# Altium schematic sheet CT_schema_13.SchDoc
size 387 x 385 mm
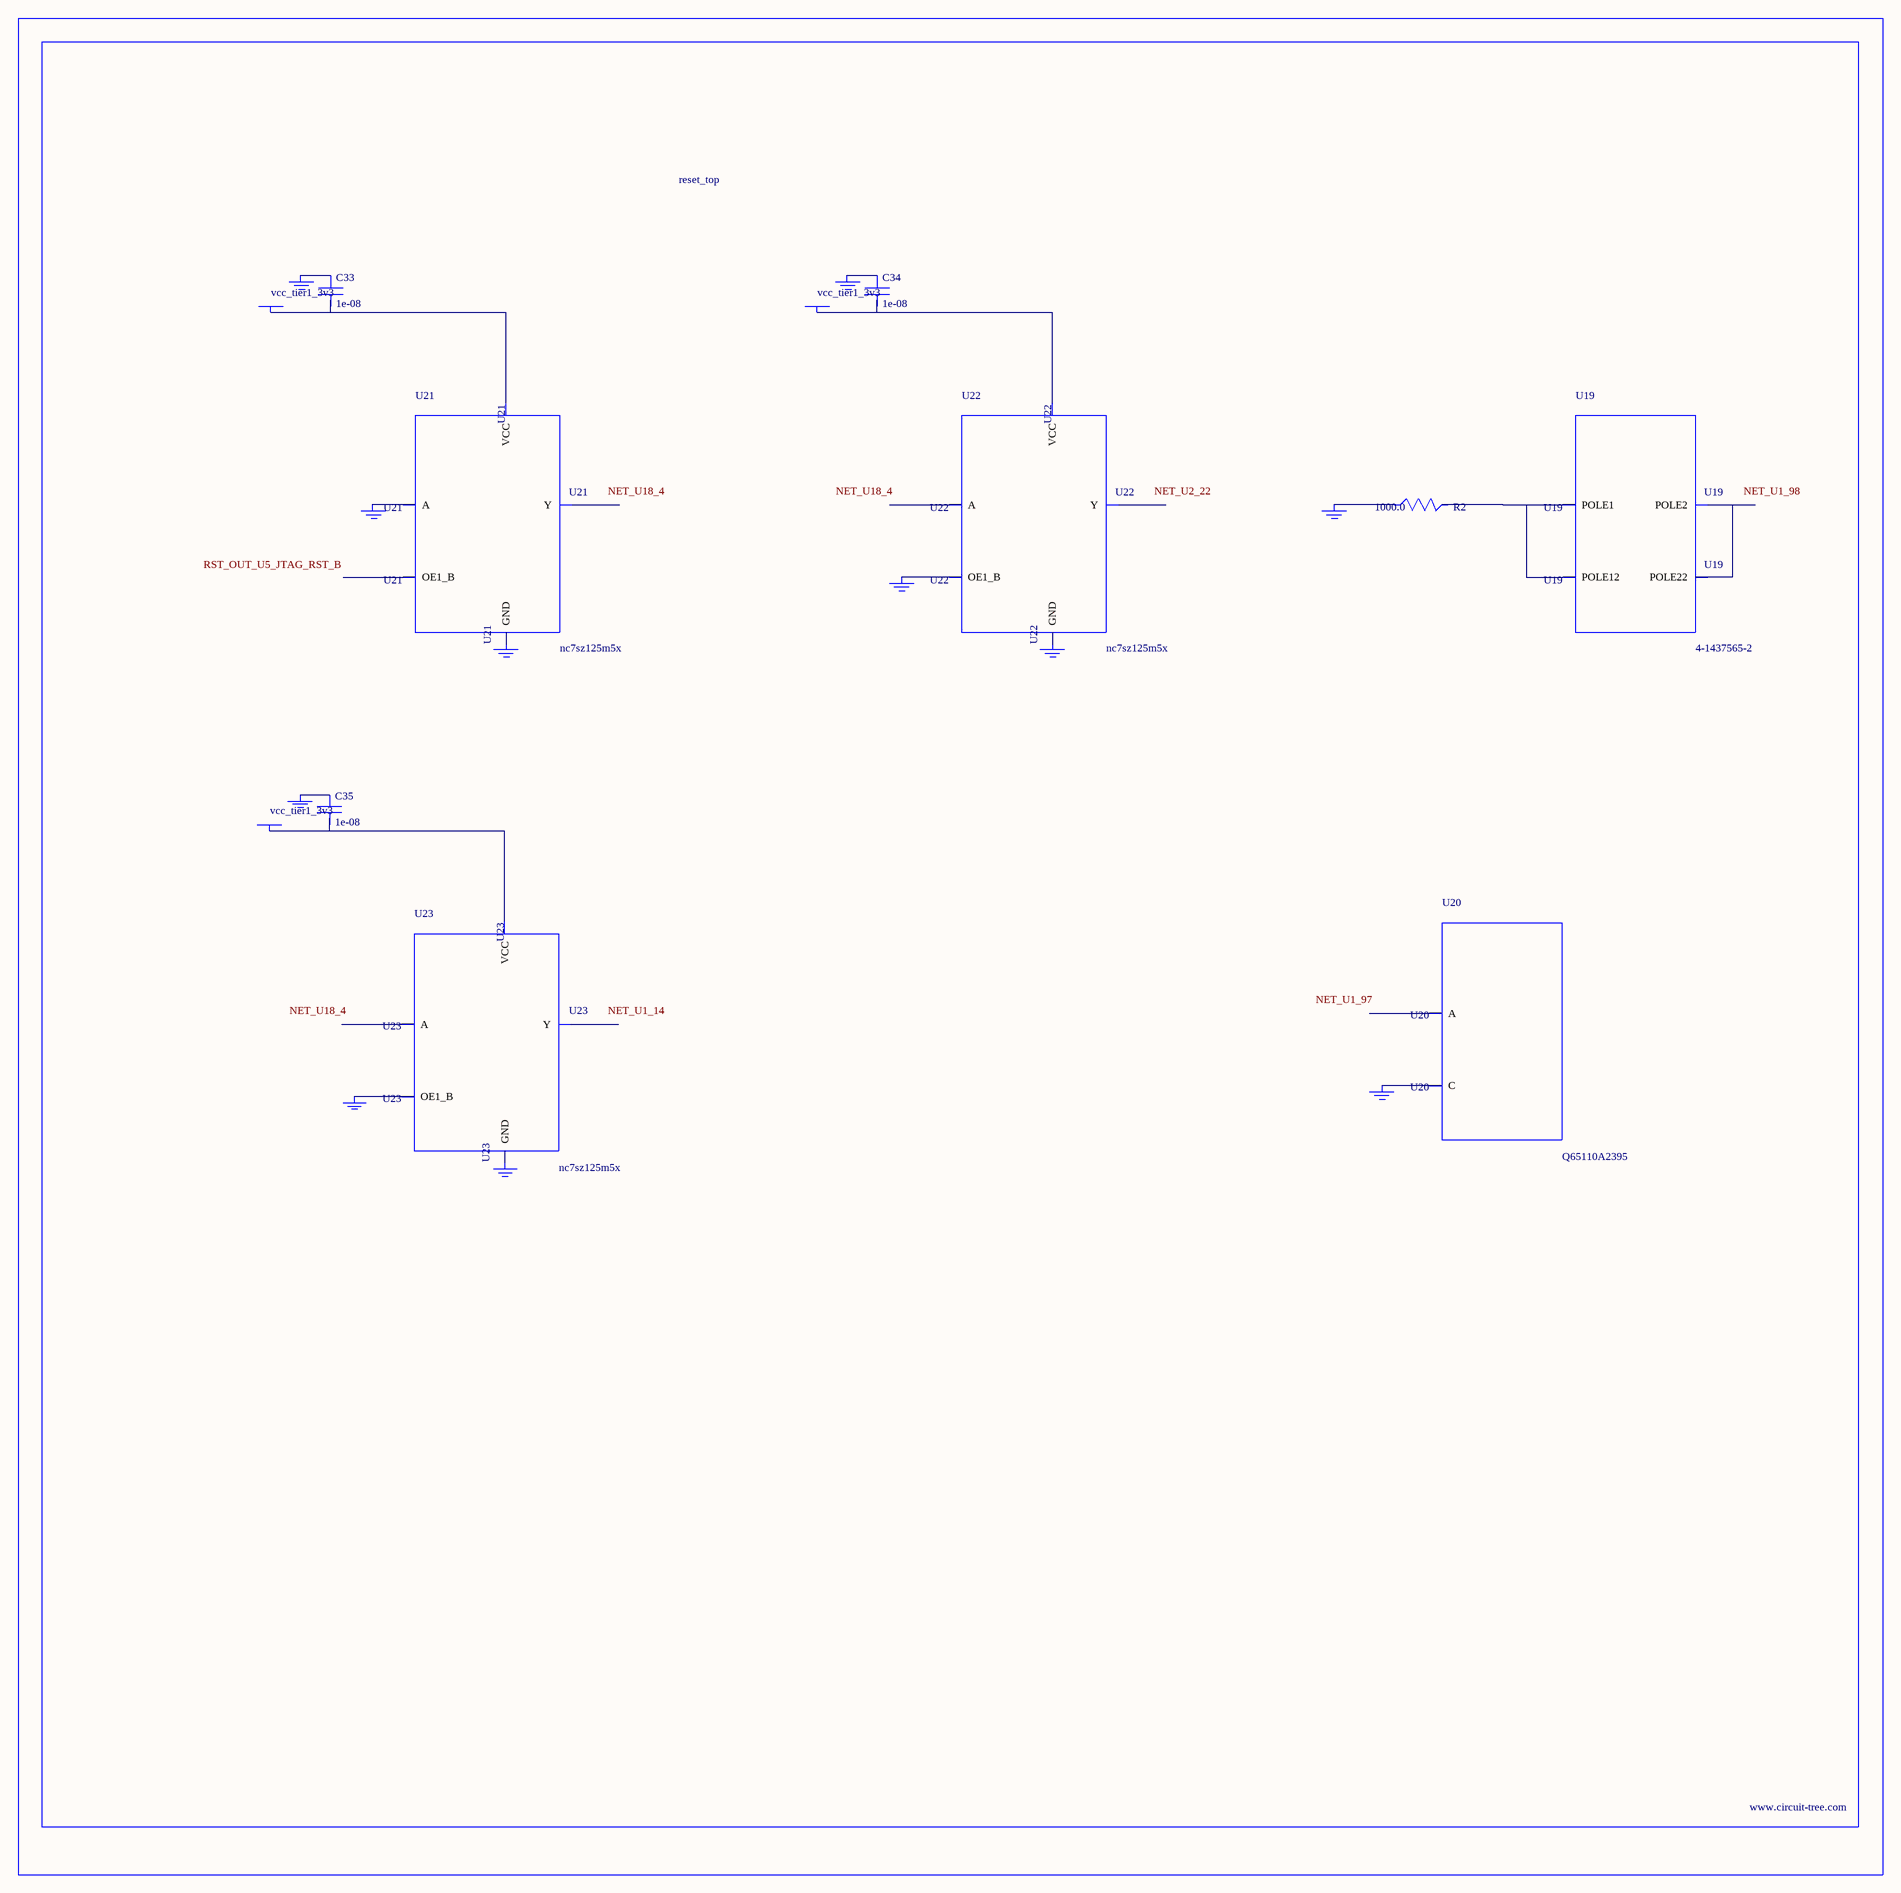
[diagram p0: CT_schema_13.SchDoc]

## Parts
BORDER12  (no value)
C33  1e-08  [C0402]
C34  1e-08  [C0402]
C35  1e-08  [C0402]
GND_INSTANCE_12_0  (no value)
GND_INSTANCE_12_1  (no value)
GND_INSTANCE_12_2  (no value)
GND_INSTANCE_12_3  (no value)
GND_INSTANCE_12_4  (no value)
GND_INSTANCE_12_5  (no value)
GND_INSTANCE_12_6  (no value)
GND_INSTANCE_12_7  (no value)
GND_INSTANCE_12_8  (no value)
GND_INSTANCE_12_9  (no value)
GND_INSTANCE_12_10  (no value)
POWER_INSTANCE_12_0  vcc_tier1_3v3
POWER_INSTANCE_12_1  vcc_tier1_3v3
POWER_INSTANCE_12_2  vcc_tier1_3v3
R2  1000.0  [R0603]
U19  4-1437565-2  [SW_4-1437565-2]
U20  Q65110A2395  [LGM67K-G1J2-24-Z]
U21  nc7sz125m5x  [NC7SZ125M5X]
U22  nc7sz125m5x  [NC7SZ125M5X]
U23  nc7sz125m5x  [NC7SZ125M5X]

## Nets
NetC33_1: C33.1 GND_INSTANCE_12_2.0(GND)
NetC33_2: C33.2 POWER_INSTANCE_12_0.0(PWR) U21.5(VCC)
NetC34_1: C34.1 GND_INSTANCE_12_5.0(GND)
NetC34_2: C34.2 POWER_INSTANCE_12_1.0(PWR) U22.5(VCC)
NetC35_1: C35.1 GND_INSTANCE_12_8.0(GND)
NetC35_2: C35.2 POWER_INSTANCE_12_2.0(PWR) U23.5(VCC)
NetGND_INSTANCE_12_0_0: GND_INSTANCE_12_0.0(GND) R2.1
NetGND_INSTANCE_12_1_0: GND_INSTANCE_12_1.0(GND) U20.C
NetGND_INSTANCE_12_3_0: GND_INSTANCE_12_3.0(GND) U21.2(A)
NetGND_INSTANCE_12_4_0: GND_INSTANCE_12_4.0(GND) U21.3(GND)
NetGND_INSTANCE_12_6_0: GND_INSTANCE_12_6.0(GND) U22.1(OE1_B)
NetGND_INSTANCE_12_7_0: GND_INSTANCE_12_7.0(GND) U22.3(GND)
NetGND_INSTANCE_12_9_0: GND_INSTANCE_12_9.0(GND) U23.1(OE1_B)
NetGND_INSTANCE_12_10_0: GND_INSTANCE_12_10.0(GND) U23.3(GND)
NetR2_2: R2.2 U19.1(POLE1) U19.2(POLE12)
NetU19_3: U19.3(POLE2) U19.4(POLE22)

Not connected (* = marked no-connect by the designer): U20 A; U21 1(OE1_B) 4(Y); U22 2(A) 4(Y); U23 2(A) 4(Y)

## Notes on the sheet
- Labels drawn without touching a wire or pin: NET_U1_14, NET_U1_97, NET_U1_98, NET_U2_22, NET_U18_4, RST_OUT_U5_JTAG_RST_B

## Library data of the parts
BORDER12 = BORDER_PAGE12
C33-C35 = C0402C103K3RAC
GND_INSTANCE_12_0-GND_INSTANCE_12_10 = GND
POWER_INSTANCE_12_0-POWER_INSTANCE_12_2 = PWR
R2 = RC0603JR-071KL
